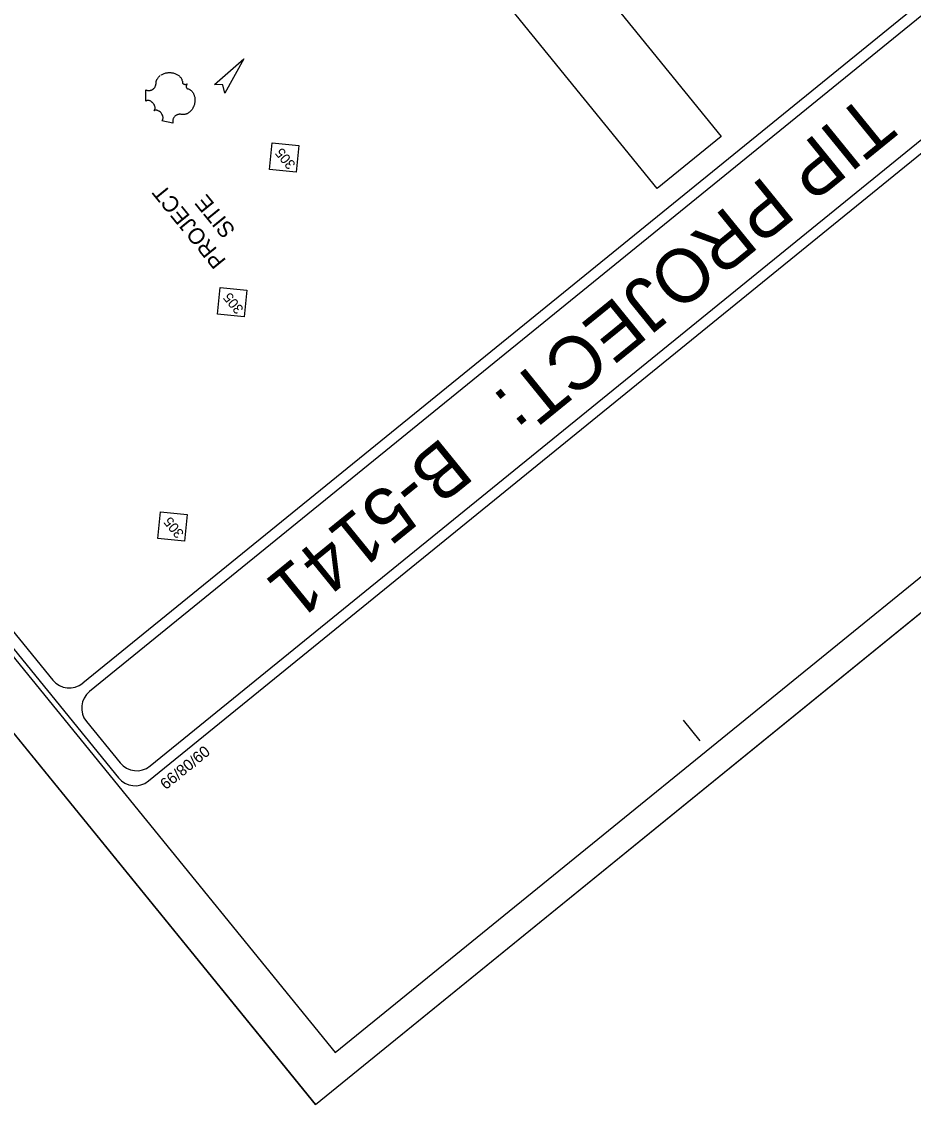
# Model space of a CAD drawing. Extents: x 2596486 to 2602076, y 851390 to 856110.
# Drawn here: x 2598058 to 2598768, y 851390 to 852253 of the extents above; entities that cross this region are included whole.
import ezdxf

# ---------------------------------------------------------------- set-up
doc = ezdxf.new("R2010")
doc.units = 0
for name, color, linetype in [('Default', 7, 'Continuous'), ('Old_Level_1', 7, 'Continuous'), ('Prop Terminator CELL', 7, 'Continuous'), ('Sheet Cutting Line CELL', 7, 'Continuous'), ('Sheet Plot Border Inside CELL', 7, 'Continuous'), ('Sheet Plot Border Outside CELL', 7, 'Continuous'), ('Sheet Title CELL', 7, 'Continuous')]:
    doc.layers.add(name, color=color, linetype=linetype)

msp = doc.modelspace()

# ---------------------------------------------------------------- linework, layer by layer
at = {"layer": 'Default'}
for p, q in [((2598165.31, 852207.31), (2598165.62, 852207.89)), ((2598165.62, 852207.89), (2598165.96, 852208.4)), ((2598165.96, 852208.4), (2598166.15, 852208.66)), ((2598166.15, 852208.66), (2598166.61, 852209.2)), ((2598166.61, 852209.2), (2598166.84, 852209.45)), ((2598166.84, 852209.45), (2598167.33, 852209.92)), ((2598167.33, 852209.92), (2598167.97, 852210.44)), ((2598168.61, 852210.88), (2598169.4, 852211.34)), ((2598169.4, 852211.34), (2598169.9, 852211.59)), ((2598169.9, 852211.59), (2598170.51, 852211.84)), ((2598170.51, 852211.84), (2598171.05, 852212.05)), ((2598171.05, 852212.05), (2598171.88, 852212.31)), ((2598171.88, 852212.31), (2598172.51, 852212.45)), ((2598172.51, 852212.45), (2598173.28, 852212.6)), ((2598173.28, 852212.6), (2598173.76, 852212.66)), ((2598173.76, 852212.66), (2598174.29, 852212.71)), ((2598174.29, 852212.71), (2598174.92, 852212.74)), ((2598174.92, 852212.74), (2598175.61, 852212.75)), ((2598175.61, 852212.75), (2598176.39, 852212.7)), ((2598176.39, 852212.7), (2598176.98, 852212.64)), ((2598176.98, 852212.64), (2598177.71, 852212.53)), ((2598177.71, 852212.53), (2598178.14, 852212.44)), ((2598178.14, 852212.44), (2598178.71, 852212.3)), ((2598178.71, 852212.3), (2598179.46, 852212.07)), ((2598179.46, 852212.07), (2598180.16, 852211.8)), ((2598180.16, 852211.8), (2598180.72, 852211.55)), ((2598180.72, 852211.55), (2598181.19, 852211.31)), ((2598181.19, 852211.31), (2598181.77, 852210.97)), ((2598181.77, 852210.97), (2598182.65, 852210.35)), ((2598182.65, 852210.35), (2598182.95, 852210.1)), ((2598182.95, 852210.1), (2598183.29, 852209.79)), ((2598183.29, 852209.79), (2598183.58, 852209.49)), ((2598183.58, 852209.49), (2598183.86, 852209.19)), ((2598183.86, 852209.19), (2598184.21, 852208.76)), ((2598184.21, 852208.76), (2598184.52, 852208.31)), ((2598184.52, 852208.31), (2598184.79, 852207.86)), ((2598184.79, 852207.86), (2598185.04, 852207.37)), ((2598156.48, 852190.06), (2598156.39, 852199.1)), ((2598156.39, 852199.1), (2598156.54, 852199.01)), ((2598156.54, 852199.01), (2598156.93, 852198.83)), ((2598156.93, 852198.83), (2598157.26, 852198.71)), ((2598160.85, 852198.81), (2598161.2, 852198.96)), ((2598161.2, 852198.96), (2598161.48, 852199.1)), ((2598161.48, 852199.1), (2598162.02, 852199.43)), ((2598162.02, 852199.43), (2598162.26, 852199.61)), ((2598162.26, 852199.61), (2598162.49, 852199.79)), ((2598162.49, 852199.79), (2598162.73, 852200)), ((2598162.73, 852200), (2598162.94, 852200.22)), ((2598162.94, 852200.22), (2598163.15, 852200.46)), ((2598163.15, 852200.46), (2598163.33, 852200.67)), ((2598163.33, 852200.67), (2598163.54, 852200.95)), ((2598163.54, 852200.95), (2598163.77, 852201.29)), ((2598163.77, 852201.29), (2598163.96, 852201.65)), ((2598163.96, 852201.65), (2598164.24, 852202.29)), ((2598164.24, 852202.29), (2598164.46, 852203.01)), ((2598164.46, 852203.01), (2598164.55, 852203.46)), ((2598164.55, 852203.46), (2598164.59, 852203.88)), ((2598164.59, 852203.88), (2598164.6, 852204.45)), ((2598164.6, 852204.45), (2598164.62, 852204.76)), ((2598164.62, 852204.76), (2598164.66, 852205.14)), ((2598164.66, 852205.14), (2598164.78, 852205.81)), ((2598164.78, 852205.81), (2598164.85, 852206.1)), ((2598164.85, 852206.1), (2598164.95, 852206.42)), ((2598164.95, 852206.42), (2598165.06, 852206.72)), ((2598165.06, 852206.72), (2598165.19, 852207.04)), ((2598165.19, 852207.04), (2598165.31, 852207.31)), ((2598185.04, 852207.37), (2598185.27, 852206.83)), ((2598185.27, 852206.83), (2598185.43, 852206.31)), ((2598185.43, 852206.31), (2598185.56, 852205.74)), ((2598185.56, 852205.74), (2598185.69, 852204.72)), ((2598185.69, 852204.72), (2598185.74, 852204.44)), ((2598185.74, 852204.44), (2598185.8, 852204.3)), ((2598185.8, 852204.3), (2598186, 852204.03)), ((2598186, 852204.03), (2598186.26, 852203.83)), ((2598186.26, 852203.83), (2598186.56, 852203.66)), ((2598186.56, 852203.66), (2598186.77, 852203.57)), ((2598186.77, 852203.57), (2598187.06, 852203.47)), ((2598187.06, 852203.47), (2598187.31, 852203.42)), ((2598187.31, 852203.42), (2598187.64, 852203.38)), ((2598187.64, 852203.38), (2598187.9, 852203.37)), ((2598187.9, 852203.37), (2598188.1, 852203.36)), ((2598188.1, 852203.36), (2598188.55, 852203.42)), ((2598188.55, 852203.42), (2598188.75, 852203.47)), ((2598188.66, 852202.15), (2598188.63, 852201.84)), ((2598188.63, 852201.84), (2598188.63, 852201.5)), ((2598188.63, 852201.5), (2598188.68, 852201.17)), ((2598188.73, 852202.52), (2598188.66, 852202.15)), ((2598188.68, 852201.17), (2598188.73, 852200.92)), ((2598188.8, 852202.78), (2598188.73, 852202.52)), ((2598188.73, 852200.92), (2598188.8, 852200.71)), ((2598188.75, 852203.47), (2598188.99, 852203.54)), ((2598188.9, 852203.05), (2598188.8, 852202.78)), ((2598188.8, 852200.71), (2598188.92, 852200.47)), ((2598189.04, 852203.34), (2598188.9, 852203.05)), ((2598188.92, 852200.47), (2598189.03, 852200.3)), ((2598188.99, 852203.54), (2598189.32, 852203.7)), ((2598189.03, 852200.3), (2598189.15, 852200.17)), ((2598189.32, 852203.7), (2598189.04, 852203.34)), ((2598189.15, 852200.17), (2598189.34, 852200.02)), ((2598189.34, 852200.02), (2598189.72, 852199.91)), ((2598189.72, 852199.91), (2598190.07, 852199.81)), ((2598190.07, 852199.81), (2598190.44, 852199.68)), ((2598190.44, 852199.68), (2598190.85, 852199.51)), ((2598190.85, 852199.51), (2598191.13, 852199.37)), ((2598191.13, 852199.37), (2598191.45, 852199.19)), ((2598191.45, 852199.19), (2598191.81, 852198.96)), ((2598191.81, 852198.96), (2598192.17, 852198.7)), ((2598156.64, 852190.19), (2598156.48, 852190.06)), ((2598156.86, 852190.32), (2598156.64, 852190.19)), ((2598157.12, 852190.44), (2598156.86, 852190.32)), ((2598157.4, 852190.52), (2598157.12, 852190.44)), ((2598157.26, 852198.71), (2598157.83, 852198.54)), ((2598157.67, 852190.59), (2598157.4, 852190.52)), ((2598157.97, 852190.61), (2598157.67, 852190.59)), ((2598157.83, 852198.54), (2598158.11, 852198.5)), ((2598158.42, 852190.6), (2598157.97, 852190.61)), ((2598158.11, 852198.5), (2598158.4, 852198.46)), ((2598158.4, 852198.46), (2598158.68, 852198.45)), ((2598158.83, 852190.54), (2598158.42, 852190.6)), ((2598158.68, 852198.45), (2598158.94, 852198.44)), ((2598159.16, 852190.47), (2598158.83, 852190.54)), ((2598158.94, 852198.44), (2598159.29, 852198.46)), ((2598159.56, 852190.33), (2598159.16, 852190.47)), ((2598159.29, 852198.46), (2598159.62, 852198.5)), ((2598160.01, 852190.14), (2598159.56, 852190.33)), ((2598159.62, 852198.5), (2598159.98, 852198.55)), ((2598159.98, 852198.55), (2598160.27, 852198.62)), ((2598160.27, 852198.62), (2598160.85, 852198.81)), ((2598192.17, 852198.7), (2598192.52, 852198.41)), ((2598192.52, 852198.41), (2598192.81, 852198.14)), ((2598192.81, 852198.14), (2598193.11, 852197.84)), ((2598193.11, 852197.84), (2598193.36, 852197.55)), ((2598193.36, 852197.55), (2598193.61, 852197.24)), ((2598193.61, 852197.24), (2598193.82, 852196.93)), ((2598193.82, 852196.93), (2598194.06, 852196.58)), ((2598194.06, 852196.58), (2598194.34, 852196.11)), ((2598194.34, 852196.11), (2598194.54, 852195.7)), ((2598194.54, 852195.7), (2598194.73, 852195.26)), ((2598194.73, 852195.26), (2598194.92, 852194.8)), ((2598194.92, 852194.8), (2598195.09, 852194.27)), ((2598195.09, 852194.27), (2598195.28, 852193.6)), ((2598195.28, 852193.6), (2598195.38, 852193.11)), ((2598195.38, 852193.11), (2598195.51, 852192.3)), ((2598195.51, 852192.3), (2598195.59, 852191.3)), ((2598195.59, 852190.5), (2598195.56, 852189.88)), ((2598195.59, 852191.3), (2598195.59, 852190.5)), ((2598160.34, 852189.97), (2598160.01, 852190.14)), ((2598160.69, 852189.76), (2598160.34, 852189.97)), ((2598161.04, 852189.5), (2598160.69, 852189.76)), ((2598161.3, 852189.29), (2598161.04, 852189.5)), ((2598161.6, 852189.02), (2598161.3, 852189.29)), ((2598161.87, 852188.77), (2598161.6, 852189.02)), ((2598162.11, 852188.51), (2598161.87, 852188.77)), ((2598162.35, 852188.21), (2598162.11, 852188.51)), ((2598162.54, 852187.96), (2598162.35, 852188.21)), ((2598162.76, 852187.65), (2598162.54, 852187.96)), ((2598162.96, 852187.32), (2598162.76, 852187.65)), ((2598163.19, 852182.44), (2598162.86, 852182.21)), ((2598162.86, 852182.21), (2598163.1, 852182.44)), ((2598163.14, 852187), (2598162.96, 852187.32)), ((2598163.1, 852182.44), (2598163.24, 852182.59)), ((2598163.31, 852186.65), (2598163.14, 852187)), ((2598163.36, 852182.52), (2598163.19, 852182.44)), ((2598163.24, 852182.59), (2598163.36, 852182.76)), ((2598163.45, 852186.3), (2598163.31, 852186.65)), ((2598163.36, 852182.76), (2598163.47, 852182.96)), ((2598163.78, 852182.68), (2598163.36, 852182.52)), ((2598163.55, 852186.02), (2598163.45, 852186.3)), ((2598163.47, 852182.96), (2598163.61, 852183.27)), ((2598163.63, 852185.73), (2598163.55, 852186.02)), ((2598163.61, 852183.27), (2598163.7, 852183.56)), ((2598163.76, 852185.12), (2598163.63, 852185.73)), ((2598163.7, 852183.56), (2598163.79, 852184.04)), ((2598163.81, 852184.53), (2598163.76, 852185.12)), ((2598164.01, 852182.72), (2598163.78, 852182.68)), ((2598163.79, 852184.04), (2598163.81, 852184.3)), ((2598163.81, 852184.3), (2598163.81, 852184.53)), ((2598164.25, 852182.75), (2598164.01, 852182.72)), ((2598164.72, 852182.76), (2598164.25, 852182.75)), ((2598165.24, 852182.69), (2598164.72, 852182.76)), ((2598165.56, 852182.61), (2598165.24, 852182.69)), ((2598165.94, 852182.48), (2598165.56, 852182.61)), ((2598166.38, 852182.3), (2598165.94, 852182.48)), ((2598166.74, 852182.1), (2598166.38, 852182.3)), ((2598167.11, 852181.87), (2598166.74, 852182.1)), ((2598167.42, 852181.64), (2598167.11, 852181.87)), ((2598168.05, 852181.11), (2598167.42, 852181.64)), ((2598192.03, 852181.9), (2598191.58, 852181.48)), ((2598192.44, 852182.34), (2598192.03, 852181.9)), ((2598192.72, 852182.67), (2598192.44, 852182.34)), ((2598193.11, 852183.16), (2598192.72, 852182.67)), ((2598193.32, 852183.45), (2598193.11, 852183.16)), ((2598193.63, 852183.93), (2598193.32, 852183.45)), ((2598193.94, 852184.45), (2598193.63, 852183.93)), ((2598194.26, 852185.05), (2598193.94, 852184.45)), ((2598194.46, 852185.49), (2598194.26, 852185.05)), ((2598194.75, 852186.21), (2598194.46, 852185.49)), ((2598194.92, 852186.68), (2598194.75, 852186.21)), ((2598195.12, 852187.35), (2598194.92, 852186.68)), ((2598195.36, 852188.34), (2598195.12, 852187.35)), ((2598195.45, 852188.93), (2598195.36, 852188.34)), ((2598195.56, 852189.88), (2598195.45, 852188.93)), ((2598168.55, 852180.58), (2598168.05, 852181.11)), ((2598168.96, 852180.06), (2598168.55, 852180.58)), ((2598169.33, 852179.48), (2598168.96, 852180.06)), ((2598169.26, 852174.37), (2598169.47, 852174.57)), ((2598178.08, 852172.44), (2598169.26, 852174.37)), ((2598169.63, 852178.92), (2598169.33, 852179.48)), ((2598169.47, 852174.57), (2598169.7, 852174.84)), ((2598169.88, 852178.33), (2598169.63, 852178.92)), ((2598169.7, 852174.84), (2598169.8, 852175)), ((2598169.8, 852175), (2598169.96, 852175.34)), ((2598170.05, 852177.76), (2598169.88, 852178.33)), ((2598169.96, 852175.34), (2598170.11, 852175.8)), ((2598170.15, 852177.23), (2598170.05, 852177.76)), ((2598170.11, 852175.8), (2598170.18, 852176.35)), ((2598170.18, 852176.89), (2598170.15, 852177.23)), ((2598170.18, 852176.35), (2598170.18, 852176.89)), ((2598177.89, 852174.63), (2598177.84, 852174.19)), ((2598177.84, 852174.19), (2598177.85, 852173.81)), ((2598177.85, 852173.81), (2598177.87, 852173.45)), ((2598177.87, 852173.45), (2598177.93, 852173.04)), ((2598177.96, 852175.09), (2598177.89, 852174.63)), ((2598177.93, 852173.04), (2598178.02, 852172.66)), ((2598178.11, 852175.59), (2598177.96, 852175.09)), ((2598178.3, 852176.1), (2598178.11, 852175.59)), ((2598178.46, 852176.44), (2598178.3, 852176.1)), ((2598178.71, 852176.87), (2598178.46, 852176.44)), ((2598178.96, 852177.21), (2598178.71, 852176.87)), ((2598179.27, 852177.58), (2598178.96, 852177.21)), ((2598179.61, 852177.93), (2598179.27, 852177.58)), ((2598179.93, 852178.2), (2598179.61, 852177.93)), ((2598180.33, 852178.51), (2598179.93, 852178.2)), ((2598180.68, 852178.72), (2598180.33, 852178.51)), ((2598181.07, 852178.93), (2598180.68, 852178.72)), ((2598181.38, 852179.07), (2598181.07, 852178.93)), ((2598181.85, 852179.25), (2598181.38, 852179.07)), ((2598182.17, 852179.34), (2598181.85, 852179.25)), ((2598182.63, 852179.44), (2598182.17, 852179.34)), ((2598182.95, 852179.49), (2598182.63, 852179.44)), ((2598183.32, 852179.53), (2598182.95, 852179.49)), ((2598183.75, 852179.54), (2598183.32, 852179.53)), ((2598184.07, 852179.53), (2598183.75, 852179.54)), ((2598184.64, 852179.46), (2598184.07, 852179.53)), ((2598185.07, 852179.37), (2598184.64, 852179.46)), ((2598185.59, 852179.31), (2598185.07, 852179.37)), ((2598186.12, 852179.27), (2598185.59, 852179.31)), ((2598186.57, 852179.28), (2598186.12, 852179.27)), ((2598187.07, 852179.33), (2598186.57, 852179.28)), ((2598187.51, 852179.4), (2598187.07, 852179.33)), ((2598188.02, 852179.52), (2598187.51, 852179.4)), ((2598188.53, 852179.67), (2598188.02, 852179.52)), ((2598188.97, 852179.83), (2598188.53, 852179.67)), ((2598189.31, 852179.98), (2598188.97, 852179.83)), ((2598189.78, 852180.21), (2598189.31, 852179.98)), ((2598190.29, 852180.51), (2598189.78, 852180.21)), ((2598190.76, 852180.82), (2598190.29, 852180.51)), ((2598191.14, 852181.11), (2598190.76, 852180.82)), ((2598191.58, 852181.48), (2598191.14, 852181.11)), ((2598178.02, 852172.66), (2598178.08, 852172.44))]:
    msp.add_line(p, q, dxfattribs=at)
for points in [[(2598276.16, 852133.28), (2598254.88, 852135.47), (2598257.07, 852156.76), (2598278.36, 852154.56)], [(2598234.78, 852017.97), (2598213.49, 852020.16), (2598215.69, 852041.45), (2598236.98, 852039.25)], [(2598187.28, 851839.18), (2598166, 851841.38), (2598168.2, 851862.67), (2598189.48, 851860.47)]]:
    msp.add_lwpolyline(points, close=True, dxfattribs=at)
at = {"layer": 'Old_Level_1'}
msp.add_lwpolyline([(2598563.84, 852120.31), (2598174.68, 852599.12), (2598225.78, 852640.65), (2598614.94, 852161.84)], close=True, dxfattribs=at)
at = {"layer": 'Prop Terminator CELL'}
msp.add_lwpolyline([(2598211.23, 852203.37), (2598234.64, 852223.77), (2598219.43, 852196.47), (2598217.68, 852202.94)], close=True, dxfattribs=at)
at = {"layer": 'Sheet Cutting Line CELL'}
for q in [(2596485.91, 853611.8), (2599742.65, 852569.65)]:
    msp.add_line((2598291.52, 851390.23), q, dxfattribs=at)
at = {"layer": 'Sheet Plot Border Inside CELL'}
msp.add_lwpolyline([(2599699.12, 852562.74), (2597912.27, 854761.23), (2596520.36, 853629.94), (2598307.2, 851431.45)], close=True, dxfattribs=at)
at = {"layer": 'Sheet Plot Border Outside CELL'}
msp.add_lwpolyline([(2596485.91, 853611.8), (2598291.52, 851390.23), (2599742.65, 852569.65), (2597937.05, 854791.22)], close=True, dxfattribs=at)
at = {"layer": 'Sheet Title CELL'}
for p, q in [((2599457.21, 852813.03), (2598111.6, 851719.37)), ((2599207.8, 852621.27), (2598106.24, 851725.97)), ((2598598.19, 851680), (2598584.79, 851696.49)), ((2598598.19, 851680), (2598584.79, 851696.49))]:
    msp.add_line(p, q, dxfattribs=at)
for points in [[(2596547.83, 853603.01), (2598134.72, 851650.5)], [(2596559.8, 853601.75), (2598082.33, 851728.47)], [(2598158.62, 851648.05), (2599517.42, 852752.43)], [(2598158.62, 851648.05), (2599517.42, 852752.43)], [(2598159.84, 851660.02), (2599505.46, 852753.67)], [(2598109.15, 851695.47), (2598135.94, 851662.48)]]:
    msp.add_lwpolyline(points, dxfattribs=at)
for centre, start, end in [((2598095.52, 851739.19), 219.10281, 309.10281), ((2598122.26, 851706.14), 129.10281, 219.10281), ((2598149.07, 851673.16), 219.10281, 309.10281), ((2598147.83, 851661.2), 219.10281, 309.10281)]:
    msp.add_arc(centre, 17, start, end, dxfattribs=at)

# ---------------------------------------------------------------- texts
at = {"layer": 'Default'}
for p in [(2598276.2, 852139.69), (2598234.81, 852024.38), (2598187.32, 851845.6)]:
    msp.add_text('305', height=7.951, rotation=129.10289, dxfattribs=at).set_placement(p)
at = {"layer": 'Old_Level_1'}
for s, p in [('PROJECT', (2598220.92, 852062.95)), ('SITE', (2598228.45, 852087.31))]:
    msp.add_text(s, height=12.75, rotation=129.10281, dxfattribs=at).set_placement(p)
at = {"layer": 'Sheet Title CELL'}
for s, height, p in [('TIP PROJECT:', 42.5, (2598730.01, 852197.05)), ('B-5141  ', 42.5, (2598392.87, 851923.03)), ('09/08/99', 8.925, (2598202.83, 851676.87))]:
    msp.add_text(s, height=height, rotation=219.10281, dxfattribs=at).set_placement(p)

doc.saveas('drawing.dxf')
